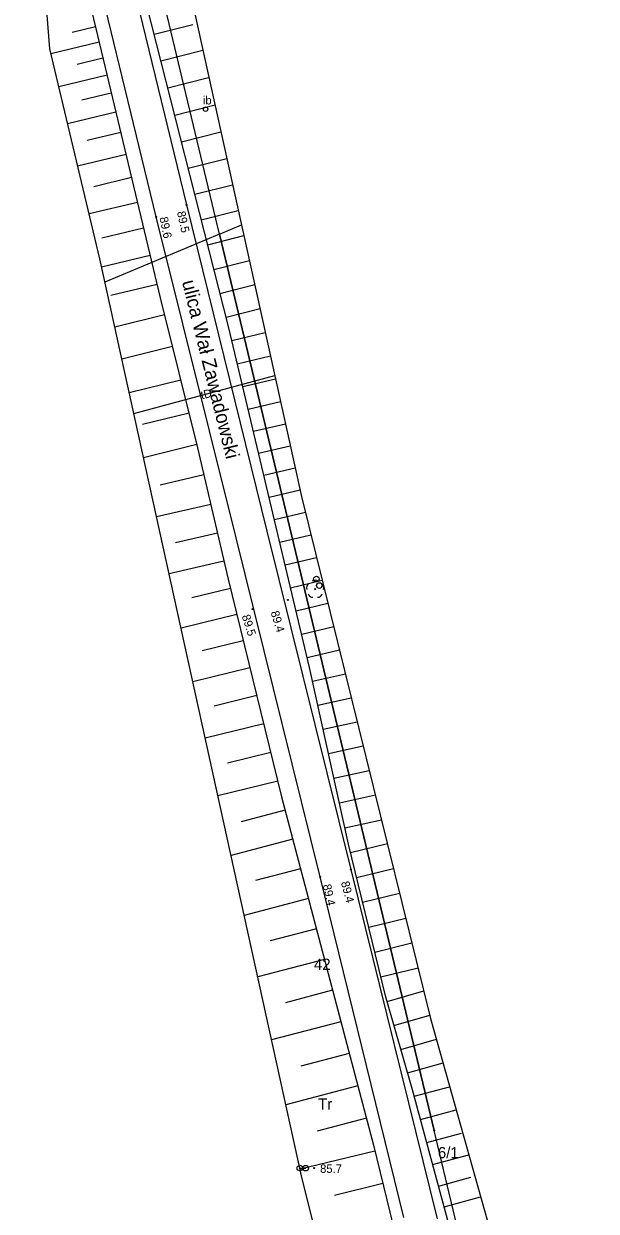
# Model space of a CAD drawing. Extents: x 7506075 to 7506993, y 5784375 to 5786367.
# Drawn here: x 7506843.8 to 7506895, y 5784640.7 to 5784747.1 of the extents above; entities that cross this region are included whole.
import ezdxf

# ---------------------------------------------------------------- set-up
doc = ezdxf.new("R2010")
doc.units = 0
for name, color, linetype in [('000 Inne (niezydentyfikowane)', 7, 'Continuous'), ('203-punkt graniczny', 7, 'Continuous'), ('210-oznaczenie konturu użytku gruntowego', 7, 'Continuous'), ('211-numer działki ewidencyjnej', 7, 'Continuous'), ('216-obręb ewidencyjny', 7, 'Continuous'), ('218-kontur użytku gruntowego', 7, 'Continuous'), ('219-działka ewidencyjna', 7, 'Continuous'), ('994-Nazwa ulicy', 7, 'Continuous'), ('drzewo liściaste', 7, 'Continuous'), ('inna budowla', 7, 'Continuous'), ('inna budowla-Atr17', 7, 'Continuous'), ('jezdnia', 7, 'Continuous'), ('pikieta naturalna', 7, 'Continuous'), ('pikieta naturalna-Atr2', 7, 'Continuous'), ('podpora (punkt)', 7, 'Continuous'), ('przewód telekomunikacyjny podziemny', 7, 'Continuous'), ('przewód telekomunikacyjny podziemny-Atr1', 7, 'Continuous'), ('skarpa umocniona', 7, 'Continuous'), ('słup przewodów napowietrznych', 7, 'Continuous')]:
    doc.layers.add(name, color=color, linetype=linetype)

# ---------------------------------------------------------------- blocks, each defined once
blk = doc.blocks.new('PW01')
blk.add_circle((0, 0), 0.045)
blk = doc.blocks.new('US25')
blk.add_circle((0, 0), 0.2)
blk = doc.blocks.new('OP021')
blk.add_circle((0, 0), 0.05)
for centre, start, end in [((-0.38, 0.124), 121.308, 202.548), ((0, 0.4), 49.272, 130.728), ((0.38, 0.124), 337.452, 58.692), ((-0.235, -0.324), 193.221, 274.871), ((0.235, -0.324), 265.129, 346.779)]:
    blk.add_arc(centre, 0.4, start, end)
blk = doc.blocks.new('IB04')
blk.add_circle((0, 0), 0.25)
blk = doc.blocks.new('US15')
blk.add_circle((0, 0), 0.25)
blk = doc.blocks.new('SM05')
blk.add_circle((0, 0), 0.25)
blk = doc.blocks.new('203')
blk.add_circle((0, 0), 0.045)

msp = doc.modelspace()

# ---------------------------------------------------------------- linework, layer by layer
at = {"layer": '000 Inne (niezydentyfikowane)'}
for p, q in [((7506855.46, 5784746.11), (7506858.92, 5784746.99)), ((7506850.2, 5784746.76), (7506848.12, 5784746.26)), ((7506850.53, 5784745.39), (7506846.216, 5784744.366)), ((7506856.06, 5784743.73), (7506859.823, 5784744.684)), ((7506850.88, 5784743.96), (7506848.57, 5784743.41)), ((7506851.24, 5784742.45), (7506846.921, 5784741.41)), ((7506856.68, 5784741.3), (7506860.32, 5784742.23)), ((7506851.62, 5784740.84), (7506849, 5784740.22)), ((7506857.3, 5784738.87), (7506860.905, 5784739.785)), ((7506852.03, 5784739.13), (7506847.71, 5784738.096)), ((7506852.47, 5784737.3), (7506849.47, 5784736.59)), ((7506857.91, 5784736.47), (7506861.439, 5784737.367)), ((7506852.94, 5784735.35), (7506848.612, 5784734.312)), ((7506858.51, 5784734.11), (7506861.964, 5784734.988)), ((7506853.43, 5784733.27), (7506850.07, 5784732.46)), ((7506859.1, 5784731.78), (7506862.483, 5784732.638)), ((7506853.96, 5784731.06), (7506849.633, 5784730.028)), ((7506859.68, 5784729.5), (7506862.99, 5784730.342)), ((7506854.52, 5784728.74), (7506850.78, 5784727.85)), ((7506860.25, 5784727.26), (7506863.489, 5784728.084)), ((7506855.1, 5784726.29), (7506850.757, 5784725.252)), ((7506860.81, 5784725.06), (7506863.978, 5784725.868)), ((7506855.72, 5784723.71), (7506851.58, 5784722.72)), ((7506861.35, 5784722.9), (7506864.459, 5784723.691)), ((7506861.89, 5784720.78), (7506864.931, 5784721.554)), ((7506856.38, 5784721), (7506851.935, 5784719.893)), ((7506862.41, 5784718.69), (7506865.406, 5784719.401)), ((7506857.09, 5784718.15), (7506852.568, 5784717.017)), ((7506862.9, 5784716.61), (7506865.866, 5784717.317)), ((7506857.84, 5784715.14), (7506853.233, 5784713.991)), ((7506863.39, 5784714.56), (7506866.32, 5784715.264)), ((7506863.87, 5784712.55), (7506866.768, 5784713.235)), ((7506858.58, 5784712.19), (7506854.43, 5784711.16)), ((7506864.34, 5784710.56), (7506867.208, 5784711.239)), ((7506859.28, 5784709.38), (7506854.508, 5784708.194)), ((7506864.81, 5784708.59), (7506867.645, 5784709.263)), ((7506859.91, 5784706.66), (7506856, 5784705.75)), ((7506865.27, 5784706.63), (7506868.078, 5784707.299)), ((7506865.74, 5784704.65), (7506868.517, 5784705.31)), ((7506860.52, 5784704.02), (7506855.673, 5784702.897)), ((7506866.22, 5784702.65), (7506868.996, 5784703.309)), ((7506861.12, 5784701.45), (7506857.37, 5784700.58)), ((7506866.7, 5784700.64), (7506869.493, 5784701.302)), ((7506867.18, 5784698.6), (7506869.994, 5784699.274)), ((7506861.7, 5784698.93), (7506856.795, 5784697.794)), ((7506867.67, 5784696.55), (7506870.501, 5784697.223)), ((7506862.28, 5784696.5), (7506858.83, 5784695.65)), ((7506868.16, 5784694.48), (7506871.011, 5784695.161)), ((7506862.85, 5784694.17), (7506857.862, 5784692.946)), ((7506868.66, 5784692.4), (7506871.525, 5784693.082)), ((7506863.43, 5784691.81), (7506859.77, 5784690.92)), ((7506869.16, 5784690.31), (7506872.042, 5784690.991)), ((7506864.02, 5784689.39), (7506858.918, 5784688.142)), ((7506869.64, 5784688.19), (7506872.576, 5784688.834)), ((7506864.64, 5784686.9), (7506860.82, 5784685.96)), ((7506870.11, 5784686.05), (7506873.102, 5784686.705)), ((7506865.26, 5784684.36), (7506860.031, 5784683.083)), ((7506870.58, 5784683.88), (7506873.635, 5784684.549)), ((7506871.06, 5784681.7), (7506874.17, 5784682.387)), ((7506865.89, 5784681.81), (7506862.01, 5784680.86)), ((7506871.54, 5784679.51), (7506874.71, 5784680.204)), ((7506866.52, 5784679.23), (7506861.166, 5784677.919)), ((7506872.03, 5784677.29), (7506875.254, 5784678.001)), ((7506867.18, 5784676.64), (7506863.25, 5784675.61)), ((7506872.52, 5784675.07), (7506875.801, 5784675.788)), ((7506867.86, 5784674.03), (7506862.341, 5784672.577)), ((7506873.03, 5784672.84), (7506876.332, 5784673.643)), ((7506868.56, 5784671.4), (7506864.54, 5784670.33)), ((7506873.57, 5784670.61), (7506876.882, 5784671.419)), ((7506874.11, 5784668.39), (7506877.429, 5784669.205)), ((7506869.26, 5784668.72), (7506863.521, 5784667.213)), ((7506869.98, 5784666.02), (7506865.85, 5784664.93)), ((7506874.66, 5784666.17), (7506877.979, 5784666.981)), ((7506875.2, 5784663.94), (7506878.529, 5784664.757)), ((7506870.7, 5784663.28), (7506864.731, 5784661.709)), ((7506875.74, 5784661.72), (7506879.079, 5784662.535)), ((7506871.43, 5784660.51), (7506867.2, 5784659.39)), ((7506876.3, 5784659.51), (7506879.592, 5784660.458)), ((7506872.17, 5784657.7), (7506865.972, 5784656.066)), ((7506876.92, 5784657.35), (7506880.133, 5784658.271)), ((7506877.53, 5784655.22), (7506880.724, 5784656.132)), ((7506872.92, 5784654.85), (7506868.58, 5784653.71)), ((7506878.14, 5784653.11), (7506881.317, 5784654.016)), ((7506873.68, 5784651.97), (7506867.246, 5784650.272)), ((7506878.73, 5784651.02), (7506881.88, 5784651.87)), ((7506874.45, 5784649.05), (7506870.06, 5784647.89)), ((7506879.29, 5784648.94), (7506882.496, 5784649.809)), ((7506879.85, 5784646.89), (7506882.96, 5784647.73)), ((7506875.21, 5784646.12), (7506868.518, 5784644.491)), ((7506880.38, 5784644.91), (7506883.623, 5784645.79)), ((7506880.9, 5784642.99), (7506883.81, 5784643.78)), ((7506875.92, 5784643.2), (7506871.61, 5784642.15)), ((7506881.41, 5784641.14), (7506884.676, 5784642.031))]:
    msp.add_line(p, q, dxfattribs=at)
at = {"layer": '216-obręb ewidencyjny'}
for points in [[(7506861.31, 5784728.22), (7506843.79, 5784801.45)], [(7506880.51, 5784647.95), (7506861.31, 5784728.22)], [(7506895.02, 5784587.37), (7506880.51, 5784647.95)]]:
    msp.add_lwpolyline(points, dxfattribs=at)
at = {"layer": '218-kontur użytku gruntowego'}
for points in [[(7506861.31, 5784728.22), (7506843.79, 5784801.45)], [(7506880.51, 5784647.95), (7506861.31, 5784728.22)], [(7506895.02, 5784587.37), (7506880.51, 5784647.95)]]:
    msp.add_lwpolyline(points, dxfattribs=at)
at = {"layer": '219-działka ewidencyjna'}
for points in [[(7506861.31, 5784728.22), (7506843.79, 5784801.45)], [(7506861.31, 5784728.22), (7506843.79, 5784801.45)], [(7506861.31, 5784728.22), (7506863.276, 5784729.046)], [(7506861.31, 5784728.22), (7506851.051, 5784723.914)], [(7506880.51, 5784647.95), (7506861.31, 5784728.22)], [(7506861.31, 5784728.22), (7506880.51, 5784647.95)], [(7506895.02, 5784587.37), (7506880.51, 5784647.95)], [(7506895.02, 5784587.37), (7506880.51, 5784647.95)]]:
    msp.add_lwpolyline(points, dxfattribs=at)
at = {"layer": 'jezdnia'}
for points in [[(7506851.3, 5784759.79), (7506858.35, 5784730.83), (7506865.55, 5784701.62), (7506873.05, 5784671.33), (7506880.78, 5784640.05)], [(7506877.8, 5784640.17), (7506870.31, 5784670.67), (7506862.8, 5784701.01), (7506855.64, 5784729.76), (7506848.57, 5784758.93)]]:
    msp.add_lwpolyline(points, dxfattribs=at)
at = {"layer": 'przewód telekomunikacyjny podziemny'}
msp.add_lwpolyline([(7506853.636, 5784712.158), (7506866.257, 5784715.547)], dxfattribs=at)
at = {"layer": 'skarpa umocniona'}
for points in [[(7506852.18, 5784779.3), (7506868.65, 5784704.71), (7506880.2, 5784658), (7506889.57, 5784624.57), (7506889.67, 5784619.16), (7506889.01, 5784613.23), (7506888.53, 5784611.18), (7506886.62, 5784618.3), (7506884.17, 5784629.55), (7506882.82, 5784635.93), (7506878.57, 5784651.6), (7506876.16, 5784660.02), (7506872.84, 5784673.6), (7506869.37, 5784689.41), (7506862.11, 5784719.93), (7506850.92, 5784763.97), (7506846.72, 5784779.03), (7506848.27, 5784785.27), (7506850.57, 5784785.8)], [(7506852.18, 5784779.3), (7506868.65, 5784704.71), (7506880.2, 5784658), (7506889.57, 5784624.57), (7506889.67, 5784619.16), (7506889.01, 5784613.23), (7506888.53, 5784611.18), (7506886.62, 5784618.3), (7506884.17, 5784629.55), (7506882.82, 5784635.93), (7506878.57, 5784651.6), (7506876.16, 5784660.02), (7506872.84, 5784673.6), (7506869.37, 5784689.41), (7506862.11, 5784719.93), (7506850.92, 5784763.97), (7506846.72, 5784779.03), (7506848.27, 5784785.27), (7506850.57, 5784785.8)], [(7506846.87, 5784760.9), (7506848.5, 5784753.88), (7506851.4, 5784741.77), (7506856.01, 5784722.5), (7506859.35, 5784709.08), (7506862.08, 5784697.31), (7506866.86, 5784677.84), (7506875.08, 5784646.66), (7506882.75, 5784615.2), (7506883.83, 5784608.06), (7506883.96, 5784604.28), (7506883.4, 5784600.35), (7506880.23, 5784597.29), (7506868.65, 5784643.89), (7506850.59, 5784726.01), (7506846.12, 5784744.79), (7506844.68, 5784762.93), (7506844.45, 5784767.49), (7506844.55, 5784770.15)], [(7506846.87, 5784760.9), (7506848.5, 5784753.88), (7506851.4, 5784741.77), (7506856.01, 5784722.5), (7506859.35, 5784709.08), (7506862.08, 5784697.31), (7506866.86, 5784677.84), (7506875.08, 5784646.66), (7506882.75, 5784615.2), (7506883.83, 5784608.06), (7506883.96, 5784604.28), (7506883.4, 5784600.35), (7506880.23, 5784597.29), (7506868.65, 5784643.89), (7506850.59, 5784726.01), (7506846.12, 5784744.79), (7506844.68, 5784762.93), (7506844.45, 5784767.49), (7506844.55, 5784770.15)]]:
    msp.add_lwpolyline(points, close=True, dxfattribs=at)
at = {"layer": 'słup przewodów napowietrznych'}
msp.add_lwpolyline([(7506868.494, 5784644.599), (7506869.02, 5784644.59)], dxfattribs=at)

# ---------------------------------------------------------------- block references
at = {"layer": '203-punkt graniczny'}
for p in [(7506861.31, 5784728.22), (7506880.51, 5784647.95)]:
    msp.add_blockref('203', p, dxfattribs=at)
at = {"layer": 'drzewo liściaste'}
msp.add_blockref('OP021', (7506869.87, 5784696.43), dxfattribs=at)
at = {"layer": 'inna budowla'}
msp.add_blockref('US25', (7506860.06, 5784739.4), dxfattribs=at)
at = {"layer": 'pikieta naturalna'}
for p in [(7506858.35, 5784730.83), (7506855.64, 5784729.76), (7506867.43, 5784695.46), (7506864.26, 5784694.64), (7506873.05, 5784671.33), (7506870.31, 5784670.67), (7506869.79, 5784644.6)]:
    msp.add_blockref('PW01', p, dxfattribs=at)
at = {"layer": 'podpora (punkt)'}
msp.add_blockref('IB04', (7506869.98, 5784697.33), dxfattribs=at)
at = {"layer": 'słup przewodów napowietrznych'}
for name, p in [('US15', (7506870.24, 5784696.75)), ('SM05', (7506868.494, 5784644.599)), ('SM05', (7506869.02, 5784644.59))]:
    msp.add_blockref(name, p, dxfattribs=at)

# ---------------------------------------------------------------- texts
at = {"layer": '210-oznaczenie konturu użytku gruntowego'}
msp.add_text('Tr', height=1, dxfattribs=at).set_placement((7506870.13, 5784649.83))
at = {"layer": '211-numer działki ewidencyjnej'}
for s, p in [('42', (7506869.76, 5784662.34)), ('6/1', (7506880.852, 5784645.48))]:
    msp.add_text(s, height=1, dxfattribs=at).set_placement(p)
at = {"layer": '994-Nazwa ulicy'}
msp.add_text('ulica Wał Zawadowski', height=1.25, rotation=284.003, dxfattribs=at).set_placement((7506857.94, 5784723.95))
at = {"layer": 'inna budowla-Atr17'}
msp.add_text('ib', height=0.75, dxfattribs=at).set_placement((7506859.822, 5784739.825))
at = {"layer": 'pikieta naturalna-Atr2'}
for s, rotation, p in [('89.5', 282.102, (7506857.5, 5784730.189)), ('89.6', 281.473, (7506855.936, 5784729.686)), ('89.5', 287.822, (7506863.289, 5784694.017)), ('89.4', 286.909, (7506865.879, 5784694.358)), ('89.4', 284.773, (7506872.167, 5784670.172)), ('89.4', 282.794, (7506870.543, 5784669.926))]:
    msp.add_text(s, height=0.75, rotation=rotation, dxfattribs=at).set_placement(p)
msp.add_text('85.7', height=0.75, dxfattribs=at).set_placement((7506870.311, 5784644.168))
at = {"layer": 'przewód telekomunikacyjny podziemny-Atr1'}
msp.add_text('tD', height=0.75, rotation=15.031, dxfattribs=at).set_placement((7506859.721, 5784713.404))

doc.saveas('drawing.dxf')
